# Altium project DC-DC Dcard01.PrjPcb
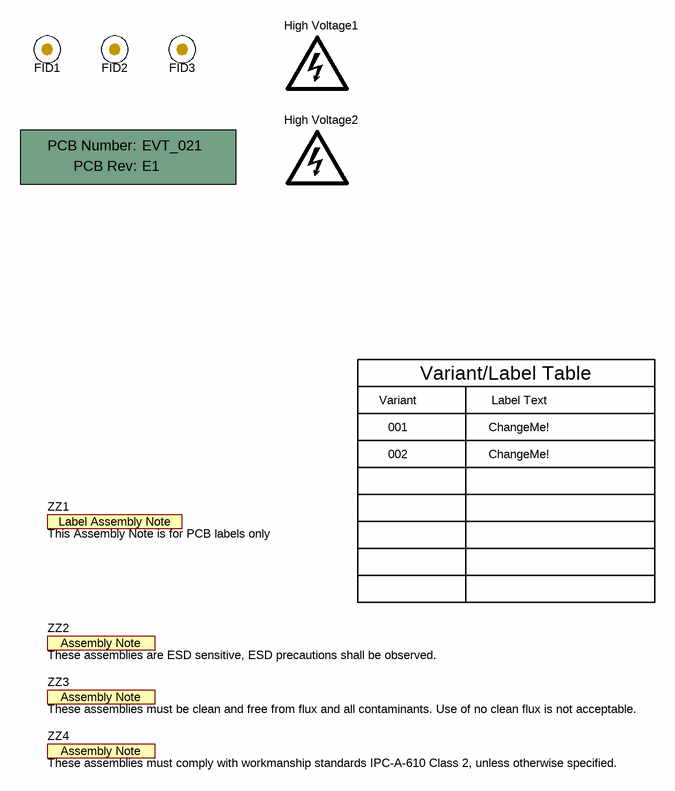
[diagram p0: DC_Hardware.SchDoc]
TID: N/A; TechSupport: http://www.ti.com/support; SCH_Rev: E1; PRJ_Title: DC-DC Gate Driver; PRJ_Number: EVT_021; PRJ_Engineer: J. Cao, X. Gong; PRJ_Customer: Public Release; PCB_Rev: E1; PCB_Layout: J. Cao, X. Gong; CopyrightYear: 2020
2 sheets, 65 parts. Net scope: global (net labels, ports and power ports of the same name join across sheets).
Board file: DC-DC Dcard01.PcbDoc
Sheets:
  DC_Hardware.SchDoc
  Gate Drive1.SchDoc

## Sheet DC_Hardware.SchDoc
size 431 x 279 mm; Date: Not shown in title block; ApprovedBy: Not shown in title block; CheckedBy: Not shown in title block; Author: Not shown in title block; CompanyName: Not shown in title block; Engineer: Not shown in title block; Organization: Not shown in title block; Address1: Not shown in title block; Address2: Not shown in title block; Address3: Not shown in title block; Address4: Not shown in title block; DocumentNumber: 1; Revision: Use project parameter SCH_Rev; SheetNumber: 2; SheetTotal: 2; PageSetup: Record=PageOptions¦CenterHorizontal=True¦CenterVertical=True¦PrintScale=1.00¦XCorrection=1.00¦YCorrection=1.00¦PrintKind=0¦BorderSize=5000000¦LeftOffset=0¦BottomOffset=0¦Orientation=2¦PaperLength=1000¦PaperWidth=1000¦Scale=100¦PaperSource=15¦PrintQuality=600¦MediaType=1¦DitherType=10¦PaperKind=Letter¦PrintScaleMode=1

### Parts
!PCB1  Printed Circuit Board  (value not drawn)  (mechanical)
FID1  Fiducial  [Fiducial10-20]  (value not drawn)
FID2  Fiducial  [Fiducial10-20]  (value not drawn)
FID3  Fiducial  [Fiducial10-20]  (value not drawn)
High_Voltage1  DANGER HIGH VOLTAGE  [IEC_HighVoltage_Small]  (value not drawn)  (no BOM)
High_Voltage2  DANGER HIGH VOLTAGE  [IEC_HighVoltage_Small]  (value not drawn)  (no BOM)
ZZ1  This Assembly Note is for PCB labels only  [AssemblyNoteLabel]  (no BOM)
ZZ2  These assemblies are ESD sensitive, ESD precautions shall be observed.  [AssemblyNote]  (no BOM)
ZZ3  These assemblies must be clean and free from flux and all contaminants. Use of no clean flux is not acceptable.  [AssemblyNote]  (no BOM)
ZZ4  These assemblies must comply with workmanship standards IPC-A-610 Class 2, unless otherwise specified.  [AssemblyNote]  (no BOM)

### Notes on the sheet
- Variant
- Variant/Label Table
- Label Text
- 001
- 002
- ChangeMe!

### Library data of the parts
!PCB1 = CMP-0003618-2: Manufacturer: Any; PartNumber: EVT_021
FID1-FID3 = CMP-0077181-1: Fiducial mark.  There is nothing to buy or mount.
High_Voltage1 High_Voltage2 = CMP-0074835-1: IEC 61010-1 High Voltage Warning; SymbolCreator: a0412235
ZZ1 = CMP-0003616-3
ZZ2 = CMP-0077236-1
ZZ3 = CMP-0077237-1
ZZ4 = CMP-0077238-1

## Sheet Gate Drive1.SchDoc
size A2; Date: Not shown in title block; ApprovedBy: Not shown in title block; CheckedBy: Not shown in title block; Author: Not shown in title block; CompanyName: Not shown in title block; Engineer: Not shown in title block; Organization: Not shown in title block; Address1: Not shown in title block; Address2: Not shown in title block; Address3: Not shown in title block; Address4: Not shown in title block; DocumentNumber: 1; Revision: Use project parameter SCH_Rev; SheetNumber: 1; SheetTotal: 2; PageSetup: Record=PageOptions¦CenterHorizontal=True¦CenterVertical=True¦PrintScale=1.00¦XCorrection=1.00¦YCorrection=1.00¦PrintKind=0¦BorderSize=5000000¦LeftOffset=0¦BottomOffset=0¦Orientation=2¦PaperLength=1000¦PaperWidth=1000¦Scale=100¦PaperSource=15¦PrintQuality=600¦MediaType=1¦DitherType=10¦PaperKind=Letter¦PrintScaleMode=1
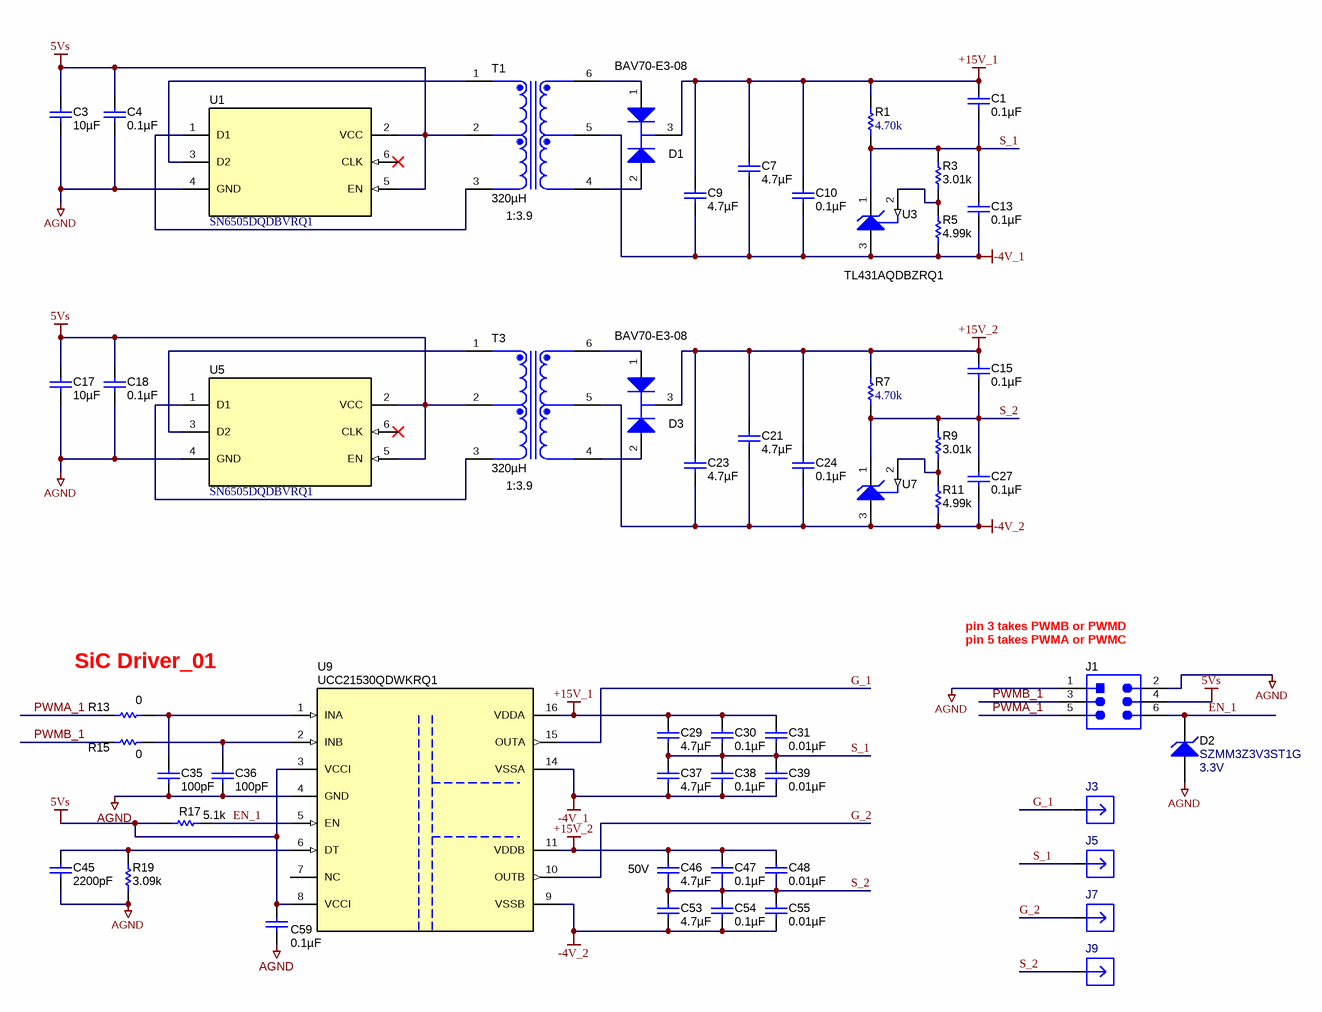
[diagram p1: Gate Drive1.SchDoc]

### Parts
C1  ValueDisplayed: 0.1µF  [0603]  (hidden comment: CGA3E2X7R1E104K080AA)
C3  ValueDisplayed: 10µF  [0603]  (hidden comment: GRT188C81A106ME13D)
C4  ValueDisplayed: 0.1µF  [0603]  (hidden comment: CGA3E2X7R1E104K080AA)
C7  ValueDisplayed: 4.7µF  [0805_HV]  (hidden comment: GRT21BR61H475KE13L)
C9  ValueDisplayed: 4.7µF  [0805_HV]  (hidden comment: GRT21BR61H475KE13L)
C10  ValueDisplayed: 0.1µF  [0603]  (hidden comment: CGA3E2X7R1E104K080AA)
C13  ValueDisplayed: 0.1µF  [0603]  (hidden comment: CGA3E2X7R1E104K080AA)
C15  ValueDisplayed: 0.1µF  [0603]  (hidden comment: CGA3E2X7R1E104K080AA)
C17  ValueDisplayed: 10µF  [0603]  (hidden comment: GRT188C81A106ME13D)
C18  ValueDisplayed: 0.1µF  [0603]  (hidden comment: CGA3E2X7R1E104K080AA)
C21  ValueDisplayed: 4.7µF  [0805_HV]  (hidden comment: GRT21BR61H475KE13L)
C23  ValueDisplayed: 4.7µF  [0805_HV]  (hidden comment: GRT21BR61H475KE13L)
C24  ValueDisplayed: 0.1µF  [0603]  (hidden comment: CGA3E2X7R1E104K080AA)
C27  ValueDisplayed: 0.1µF  [0603]  (hidden comment: CGA3E2X7R1E104K080AA)
C29  ValueDisplayed: 4.7µF  [0805_HV]  (hidden comment: GRT21BR61H475KE13L)
C30  ValueDisplayed: 0.1µF  [0603]  (hidden comment: CGA3E2X7R1E104K080AA)
C31  ValueDisplayed: 0.01µF  [0603]  (hidden comment: CGA3E2C0G1H103J080AA)
C35  ValueDisplayed: 100pF  [0603]  (hidden comment: GCM1885C2A101JA16D)
C36  ValueDisplayed: 100pF  [0603]  (hidden comment: GCM1885C2A101JA16D)
C37  ValueDisplayed: 4.7µF  [0805_HV]  (hidden comment: GRT21BR61H475KE13L)
C38  ValueDisplayed: 0.1µF  [0603]  (hidden comment: CGA3E2X7R1E104K080AA)
C39  ValueDisplayed: 0.01µF  [0603]  (hidden comment: CGA3E2C0G1H103J080AA)
C45  ValueDisplayed: 2200pF  [0603]  (hidden comment: GRM188R71C222KA01D)
C46  ValueDisplayed: 4.7µF  Value2: 50V  [0805_HV]  (hidden comment: GRT21BR61H475KE13L)
C47  ValueDisplayed: 0.1µF  [0603]  (hidden comment: CGA3E2X7R1E104K080AA)
C48  ValueDisplayed: 0.01µF  [0603]  (hidden comment: CGA3E2C0G1H103J080AA)
C53  ValueDisplayed: 4.7µF  [0805_HV]  (hidden comment: GRT21BR61H475KE13L)
C54  ValueDisplayed: 0.1µF  [0603]  (hidden comment: CGA3E2X7R1E104K080AA)
C55  ValueDisplayed: 0.01µF  [0603]  (hidden comment: CGA3E2C0G1H103J080AA)
C59  ValueDisplayed: 0.1µF  [0603]  (hidden comment: CGA3E2X7R1E104K080AA)
D1  BAV70-E3-08  [SOT-23]
D2  SZMM3Z3V3ST1G  value 3.3V  [SOD-323]
D3  BAV70-E3-08  [SOT-23]
J1  90122-0763  [Molex_90122-0763]  (value not drawn)
J3  3620-2-32-15-00-00-08-0  [Mill-Max_3620-2-32-xx-00-00-08-0]  (value not drawn)
J5  3620-2-32-15-00-00-08-0  [Mill-Max_3620-2-32-xx-00-00-08-0]  (value not drawn)
J7  3620-2-32-15-00-00-08-0  [Mill-Max_3620-2-32-xx-00-00-08-0]  (value not drawn)
J9  3620-2-32-15-00-00-08-0  [Mill-Max_3620-2-32-xx-00-00-08-0]  (value not drawn)
R1  ValueDisplayed: 4.70k  [0805_HV]  (hidden comment: ERJ-P06F4701V)
R3  ValueDisplayed: 3.01k  [0603]  (hidden comment: RT0603DRE073K01L)
R5  ValueDisplayed: 4.99k  [0603]  (hidden comment: RT0603DRE074K99L)
R7  ValueDisplayed: 4.70k  [0805_HV]  (hidden comment: ERJ-P06F4701V)
R9  ValueDisplayed: 3.01k  [0603]  (hidden comment: RT0603DRE073K01L)
R11  ValueDisplayed: 4.99k  [0603]  (hidden comment: RT0603DRE074K99L)
R13  ValueDisplayed: 0  [0603]  (hidden comment: CRCW06030000Z0EA)
R15  ValueDisplayed: 0  [0603]  (hidden comment: CRCW06030000Z0EA)
R17  ValueDisplayed: 5.1k  [0603]  (hidden comment: RC0603JR-075K1L)
R19  ValueDisplayed: 3.09k  [0603]  (hidden comment: CRCW06033K09FKEA)
T1  Ind_H: 320µH  [Wurth_750317722]  (hidden comment: 750317722)
T3  Ind_H: 320µH  [Wurth_750317722]  (hidden comment: 750317722)
U1  SN6505DQDBVRQ1  [DBV0006A_N]
U3  TL431AQDBZRQ1  [DBZ0003A_N]
U5  SN6505DQDBVRQ1  [DBV0006A_N]
U7  TL431AQDBZRQ1  [DBZ0003A_N]  (value not drawn)
U9  UCC21530QDWKRQ1  [DWK0014A]

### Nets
5Vs: C3.1 C4.1 C17.1 C18.1 C59.1 J1.4 R17.1 T1.2 T3.2 U1.2(VCC) U1.5(EN) U5.2(VCC) U5.5(EN) U9.3(VCCI) U9.8(VCCI)
+15V_1: C1.1 C7.1 C9.1 C10.1 C29.1 C30.1 C31.1 D1.3(C) R1.2 U9.16(VDDA)
+15V_2: C15.1 C21.1 C23.1 C24.1 C46.1 C47.1 C48.1 D3.3(C) R7.2 U9.11(VDDB)
-4V_1: C7.2 C9.2 C10.2 C13.2 C37.2 C38.2 C39.2 R5.1 T1.5 U3.3(ANODE) U9.14(VSSA)
-4V_2: C21.2 C23.2 C24.2 C27.2 C53.2 C54.2 C55.2 R11.1 T3.5 U7.3(ANODE) U9.9(VSSB)
AGND: C3.2 C4.2 C17.2 C18.2 C35.2 C36.2 C45.2 C59.2 D2.2(A) J1.1 J1.2 R19.1 U1.4(GND) U5.4(GND) U9.4(GND)
EN_1: D2.1(K) J1.6 R17.2 U9.5(EN)
G_1: J3.1 U9.15(OUTA)
G_2: J7.1 U9.10(OUTB)
PWMA_1: J1.5 R13.2
PWMB_1: J1.3 R15.2
S_1: C1.2 C13.1 C29.2 C30.2 C31.2 C37.1 C38.1 C39.1 J5.1 R1.1 R3.2 U3.1(CATHODE)
S_2: C15.2 C27.1 C46.2 C47.2 C48.2 C53.1 C54.1 C55.1 J9.1 R7.1 R9.2 U7.1(CATHODE)
NetC35_1: C35.1 R13.1 U9.1(INA)
NetC36_1: C36.1 R15.1 U9.2(INB)
NetC45_1: C45.1 R19.2 U9.6(DT)
NetD1_1: D1.1(A) T1.6
NetD1_2: D1.2(K) T1.4
NetD3_1: D3.1(A) T3.6
NetD3_2: D3.2(K) T3.4
NetR3_1: R3.1 R5.2 U3.2(REF)
NetR9_1: R9.1 R11.2 U7.2(REF)
NetT1_1: T1.1 U1.3(D2)
NetT1_3: T1.3 U1.1(D1)
NetT3_1: T3.1 U5.3(D2)
NetT3_3: T3.3 U5.1(D1)

Not connected (* = marked no-connect by the designer): U1 6(CLK)*; U5 6(CLK)*; U9 7(NC)

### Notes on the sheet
- (near T1) 1:3.9
- (near T3) 1:3.9
- (near R13) SiC Driver_01
- pin 3 takes PWMB or PWMD
- (near J1) pin 5 takes PWMA or PWMC

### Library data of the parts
C1 C4 C10 C13 C15 C18 C24 C27 C30 C38 C47 C54 C59 = CGA3E2X7R1E104K080AA: CAP, CERM, 0.1 µF, 25 V,+/- 10%, X7R, AEC-Q200 Grade 1, 0603; Manufacturer: TDK; Polarized: N; CompType: Capacitor; Value: 0.1uF; U/M: EA; Cap_F: 0.0000001; Tolerance_%: 10; VDC_V: 25; Value2: 25V; TaMin_C: -55; TaMax_C: 125; SizeArea_mm2: 1.28; SizeAreaWB_mm2: 4.68; SizeX_mm: 1.6; SizeY_mm: 0.8; SizeZ_mm: 1; AEC Category: Q200; AEC Qualified: Y
C3 C17 = GRT188C81A106ME13D: CAP, CERM, 10 µF, 10 V,+/- 20%, X6S, AEC-Q200 Grade 2, 0603; Manufacturer: MuRata; Polarized: N; CompType: Capacitor; Value: 10uF; U/M: EA; Cap_F: 0.00001; Tolerance_%: 20; VDC_V: 10; Value2: 10V; TaMin_C: -55; TaMax_C: 105; SizeArea_mm2: 1.28; SizeAreaWB_mm2: 4.68; SizeX_mm: 1.6; SizeY_mm: 0.8; SizeZ_mm: 1; AEC Category: Q200; AEC Qualified: Y; AEC Grade: 2; Green_Lifecycle: Active; Green_REACh: Passed
C7 C9 C21 C23 C29 C37 C53 = GRT21BR61H475KE13L: CAP, CERM, 4.7 µF, 50 V,+/- 10%, X5R, AEC-Q200 Grade 3, 0805; Manufacturer: MuRata; Polarized: N; CompType: Capacitor; Value: 4.7uF; U/M: EA; Cap_F: 0.0000047; Tolerance_%: 10; VDC_V: 50; Value2: 50V; TaMin_C: -55; TaMax_C: 85; Cap_Case: 0805; SizeArea_mm2: 2.5; SizeAreaWB_mm2: 6.75; SizeX_mm: 2; SizeY_mm: 1.25; SizeZ_mm: 1.45; AEC Category: Q200; AEC Qualified: Y; AEC Grade: 3
C31 C39 C48 C55 = CGA3E2C0G1H103J080AA: CAP, CERM, 0.01 µF, 50 V,+/- 5%, C0G/NP0, AEC-Q200 Grade 1, 0603; Manufacturer: TDK; Polarized: N; CompType: Capacitor; Value: 0.01uF; U/M: EA; Cap_F: 0.00000001; Tolerance_%: 5; VDC_V: 50; Value2: 50V; TaMin_C: -55; TaMax_C: 125; SizeArea_mm2: 1.28; SizeAreaWB_mm2: 4.68; SizeX_mm: 1.6; SizeY_mm: 0.8; SizeZ_mm: 1; AEC Category: Q200; AEC Qualified: Y; Green_Lifecycle: Active; Green_REACh: Passed
C35 C36 = GCM1885C2A101JA16D: CAP, CERM, 100 pF, 100 V,+/- 5%, C0G/NP0, AEC-Q200 Grade 1, 0603; Manufacturer: MuRata; Polarized: N; CompType: Capacitor; Value: 100pF; U/M: EA; Cap_F: 0.0000000001; Tolerance_%: 5; VDC_V: 100; Value2: 100V; TaMin_C: -55; TaMax_C: 125; SizeArea_mm2: 1.28; SizeAreaWB_mm2: 4.68; SizeX_mm: 1.6; SizeY_mm: 0.8; SizeZ_mm: 1; AEC Category: Q200; AEC Qualified: Y
C45 = GRM188R71C222KA01D: CAP, CERM, 2200 pF, 16 V,+/- 10%, X7R, 0603; Manufacturer: MuRata; Polarized: N; CompType: Capacitor; Value: 2200pF; U/M: EA; Cap_F: 0.0000000022; Tolerance_%: 10; VDC_V: 16; Value2: 16V; TaMin_C: -55; TaMax_C: 125; SizeArea_mm2: 1.28; SizeAreaWB_mm2: 4.68; SizeX_mm: 1.6; SizeY_mm: 0.8; SizeZ_mm: 1; AEC Category: Q200; Green_Lifecycle: Active; Green_REACh: Passed
C46 = GRT21BR61H475KE13L: CAP, CERM, 4.7 µF, 50 V,+/- 10%, X5R, AEC-Q200 Grade 3, 0805; Manufacturer: MuRata; Polarized: N; CompType: Capacitor; Value: 4.7uF; U/M: EA; Cap_F: 0.0000047; Tolerance_%: 10; VDC_V: 50; TaMin_C: -55; TaMax_C: 85; Cap_Case: 0805; SizeArea_mm2: 2.5; SizeAreaWB_mm2: 6.75; SizeX_mm: 2; SizeY_mm: 1.25; SizeZ_mm: 1.45; AEC Category: Q200; AEC Qualified: Y; AEC Grade: 3
D1 D3 = BAV70-E3-08: Diode, Switching, 70 V, 0.25 A, AEC-Q101, SOT-23; Manufacturer: Vishay-Semiconductor; SymbolCreator: a0412235; U/M: EA; Vf_V: 1.25; Value: 70V; Value1: 0.25A; Value2: 1.25V; Io_A: 0.25; Vr_V: 70; TJmax_C: 150; SizeAreaWB_mm2: 14; SizeArea_mm2: 7.5; SizeX_mm: 2.5; SizeY_mm: 3; SizeZ_mm: 1.1; AEC Category: Q101; AEC Qualified: Y; Green_Lifecycle: Not Set; Green_REACh: Incomplete
D2 = CMP-0085730-1: Diode, Zener, 3.3 V, 300 mW, AEC-Q101, SOD-323; Manufacturer: ON Semiconductor; RJA_CperW: 416; AEC Qualified: Y; SizeArea_mm2: 3.645; SizeX_mm: 2.7; SizeY_mm: 1.35; SizeZ_mm: 1; AEC Category: Q101; SizeAreaWB_mm2: 8.695; Power_W: 300mW; Value1: 0.3W
J1 = CMP-0077741-1: Header, 2.54mm, 3x2, Gold, R/A, TH; PartNumber: M20-9950345; Manufacturer: Harwin; Pitch_mm: 2.54; Gender: Male; Cert_UL: Y; Current_A: 3A; Voltage_V: 350V; Shrouded: N; Row_Count: 2
J3 J5 J7 J9 = CMP-0055044-1: Manufacturer: Mill-Max; CNHeader: FALSE; Gender: Male; CompType: PCB Pin; Row_Count: 1; ContactFinish: Gold
R1 R7 = CMP-0021852-2: RES, 4.70 k, 1%, 0.5 W, AEC-Q200 Grade 0, 0805; Manufacturer: Panasonic; Power_W: 500mW; TempCo: 100 ppm/C; Value_Code: 4k70; U/M: EA; Value: 4.70k; Res_ohm: 4.7k; SizeX_mm: 2; SizeY_mm: 1.25; SizeZ_mm: 1.45; Value2: 0.5W; SizeArea_mm2: 2.5; AEC Qualified: Y; VDC_V: 400V; AEC Grade: 0; AEC Category: Q200
R3 R9 = RT0603DRE073K01L: RES, 3.01 k, 0.5%, 0.1 W, 0603; Manufacturer: Yageo America; CompType: Resistor; Value: 3.01k; Res_ohm: 3010; Value_Code: 3k01; Tolerance_%: 0.5; Power_W: 0.1; Value2: 0.1W; VDC_V: 75; TempCo: 50 ppm/C; SizeArea_mm2: 1.28; SizeX_mm: 1.6; SizeY_mm: 0.8; SizeZ_mm: 1; EIA_Code: E192; U/M: EA; AEC Category: Q200
R5 R11 = RT0603DRE074K99L: RES, 4.99 k, 0.5%, 0.1 W, 0603; Manufacturer: Yageo America; CompType: Resistor; Value: 4.99k; Res_ohm: 4990; Value_Code: 4k99; Tolerance_%: 0.5; Power_W: 0.1; Value2: 0.1W; VDC_V: 75; TempCo: 50 ppm/C; SizeArea_mm2: 1.28; SizeX_mm: 1.6; SizeY_mm: 0.8; SizeZ_mm: 1; EIA_Code: E192; U/M: EA; AEC Category: Q200; Green_Lifecycle: Active; Green_REACh: Passed
R13 R15 = CRCW06030000Z0EA: RES, 0, 5%, 0.1 W, 0603; Manufacturer: Vishay-Dale; CompType: Resistor; Value: 0; Value_Code: 0000; Tolerance_%: 5; Power_W: 0.1; Value2: 0.1W; VDC_V: 75; TempCo: 200 ppm/C; SizeArea_mm2: 1.28; SizeX_mm: 1.6; SizeY_mm: 0.8; SizeZ_mm: 1; EIA_Code: E24; U/M: EA; AEC Category: Q200; Green_Lifecycle: Active; Green_REACh: Passed
R17 = RC0603JR-075K1L: RES, 5.1 k, 5%, 0.1 W, 0603; Manufacturer: Yageo America; CompType: Resistor; Value: 5.1k; Res_ohm: 5100; Value_Code: 5k10; Tolerance_%: 5; Power_W: 0.1; Value2: 0.1W; VDC_V: 50; TempCo: 100 ppm/C; SizeArea_mm2: 1.28; SizeX_mm: 1.6; SizeY_mm: 0.8; SizeZ_mm: 1; EIA_Code: E24; U/M: EA; AEC Category: Q200
R19 = CRCW06033K09FKEA: RES, 3.09 k, 1%, 0.1 W, 0603; Manufacturer: Vishay-Dale; CompType: Resistor; Value: 3.09k; Res_ohm: 3090; Value_Code: 3k09; Tolerance_%: 1; Power_W: 0.1; Value2: 0.1W; VDC_V: 75; TempCo: 100 ppm/C; SizeArea_mm2: 1.28; SizeX_mm: 1.6; SizeY_mm: 0.8; EIA_Code: E96; U/M: EA; AEC Category: Q200; Green_Lifecycle: Active; Green_REACh: Passed
T1 T3 = CMP-0081994-1: Transformer, 320 uH, SMD; Manufacturer: Wurth Elektronik; SizeAreaWB_mm2: 108.7758; SizeArea_mm2: 70.3958; AEC Qualified: N; Lp: 320; AEC Category: Q200; SizeZ_mm: 4.19; SizeY_mm: 6.73; Ns1toNp: 4.18; Rsec1_ohm: 1.15; DCR_ohm: 0.4; SizeX_mm: 10.46
U1 U5 = CMP-0860735-1: SN6505DQDBVRQ1, DBV0006A (SOT-23-6); Alternate PartNumber: SN6505DQDBVTQ1; Alternate Manufacturer: Texas Instruments; CompType: IC; SizeAreaWB_mm2: 14.82; SizeArea_mm2: 8.12; SizeZ_mm: 1.45; SizeY_mm: 2.9; SizeX_mm: 2.8; AEC Category: Q200
U3 U7 = TL431AQDBZRQ1: Automotive Catalog Adjustable Precision Shunt Regulator, 34 ppm / degC, 100 mA, -40 to 125 degC, 3-pin SOT-23 (DBZ), Green (RoHS & no Sb/Br); Manufacturer: Texas Instruments; Alternate PartNumber: Equivalent; Initial Accuracy @ 25/deg C(%): 1; Iout/Iz(Max)(mA): 100; Min Iz for Regulation(uA): 600; SubFamily: Shunt Voltage Reference; Temp Coeff(Typ)(ppm/ degree C): 34; VO Adj(Max)(V): 36; VO Adj(Min)(V): 2.495
U9 = CMP-0083997-1: 4-A, 6-A, 5.7-kVRMS Isolated Dual-Channel Gate Driver with Enable, DWK0014A (SOIC-14); Alternate PartNumber: UCC21530QDWKQ1; Alternate Manufacturer: Texas Instruments; SizeAreaWB_mm2: 151.29; SizeZ_mm: 2.65; SizeX_mm: 10.3; SizeArea_mm2: 106.09; CompType: IC; AEC Qualified: Y; AEC Category: Q200

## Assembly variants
001: not fitted C86 FID1 FID2 FID3 R93 R133 R161 R163 R165 R167 R173 R175 R177 R179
